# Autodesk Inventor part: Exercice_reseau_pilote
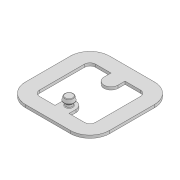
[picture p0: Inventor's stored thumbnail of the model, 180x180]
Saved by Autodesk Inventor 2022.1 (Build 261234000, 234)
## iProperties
Created: 2021-06
Part Number: Exercice_reseau_pilote
Material: Générique
Document SubType Name: Modélisation
Designer: Fabian
Density: 1 g/cm^3
Appearance: Par défaut
Sheet Metal Rule: Par défaut
Author: Fabian
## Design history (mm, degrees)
sketch "Esquisse1"
  geometry: L1 (-80, 100)-(80, 100); L2 (100, 80)-(100, -80); L3 (80, -100)-(-80, -100); L4 (-100, -80)-(-100, 80); L5 (-100, 100)-(100, -100); L6 (100, 100)-(-100, -100); L7 (150, -80)-(150, 80); L8 (80, 150)-(-80, 150); L9 (-150, 80)-(-150, -80); L10 (-80, -150)-(80, -150); L11 (25, 100)-(25, 75); L12 (-25, 75)-(-25, 100); L13 (100, 0)-(-100, 0); L14 (25, -100)-(25, -75); L15 (-25, -75)-(-25, -100); A1 r 20 centre (80, 80) between (100, 80) and (80, 100); A2 r 20 centre (80, -80) between (80, -100) and (100, -80); A3 r 20 centre (-80, 80) between (-80, 100) and (-100, 80); A4 r 20 centre (-80, -80) between (-100, -80) and (-80, -100); A5 r 70 centre (80, 80) between (150, 80) and (80, 150); A6 r 70 centre (-80, 80) between (-80, 150) and (-150, 80); A7 r 70 centre (-80, -80) between (-150, -80) and (-80, -150); A8 r 70 centre (80, -80) between (80, -150) and (150, -80); A9 r 25 centre (0, 75) between (0, 50) and (25, 75); A10 r 25 centre (0, 75) between (-25, 75) and (0, 50); A11 r 25 centre (0, -75) between (25, -75) and (0, -50); A12 r 25 centre (0, -75) between (0, -50) and (-25, -75); 12 further points
  constraints: 30 end point, 24 point on circle, 14 point on line, 12 centre point, 11 symmetric about line, 10 tangent, 5 midpoint, 4 equal radius, 4 parallel, 4 perpendicular, 2 vertical, 1 horizontal, 1 vertical alignment, 17 other
  dimensions: "d1" = 200 distance of L6.start L5.end; "d4" = 50 distance between parallel lines of L2 L7 (= 0.25 x d1); "d6" = 50 distance of point (25, 50) point (-25, 50) (= d4); "d7" = 25 radius of A9; "d8" = 50 dimension on L1 (= d6); "d9" = 20 radius of A1
extrude "Extrusion1" new body sketch "Esquisse1" distance "d10" = 10; taper "d11" = 0 deg
sketch "Esquisse3"
  geometry: L1 (-150, 80)-(-150, -80) reference; L2 (-100, -80)-(-100, 80) reference; L3 (100, 80)-(100, -80) reference; L4 (150, -80)-(150, 80) reference; A1 r 25 centre (0, -75) between (25, -75) and (-25, -75) reference; 1 further point
  constraints: 1 coincident
sketch "Esquisse4"
  geometry: L1 (10, 75)-(40, 75); L2 (40, 75)-(40, 90); L3 (40, 90)-(26, 93.5); L4 (26, 93.5)-(20, 86.5); L5 (20, 86.5)-(10, 86.5); L6 (10, 86.5)-(10, 75); 1 further point
  constraints: 12 end point, 2 horizontal, 1 perpendicular, 1 vertical
  dimensions: "d12" = 30 distance of L1.start L1.end; "d13" = 23 diameter of L5 L1; "d15" = 30 horizontal distance of L2.end L1; "d16" = 37 diameter of L3.end L1; "d17" = 10 distance of L4.end L5.end; "d18" = 16 distance from line of L6 L3.end
revolve "Révolution1" sketch "Esquisse4" stored, may be unused: angle "d19" = 90 deg
fillet "Congé1" dims "d20" = 2
node "Solide2"
other parameters: "Epaisseur" = 3.048 (derived), "FacteurX" = 4.4, "RayonPli" = 3.048 (= Epaisseur), "LargeurGrugeage" = 3.048 (= Epaisseur), "ProfondeurGrugeage" = 1.524 (= 0.5 x Epaisseur), "TailleGrugeage" = 12.192 (= 4 x Epaisseur), "JeuJointure" = 0.01, "RestesMinimum" = 6.096 (= 2 x Epaisseur), "Rayondetransition" = 3.048 (= RayonPli), "TailleRayonJacobi" = 3.048 (= RayonPli), "TailleJeu" = 3.048 (= Epaisseur)
